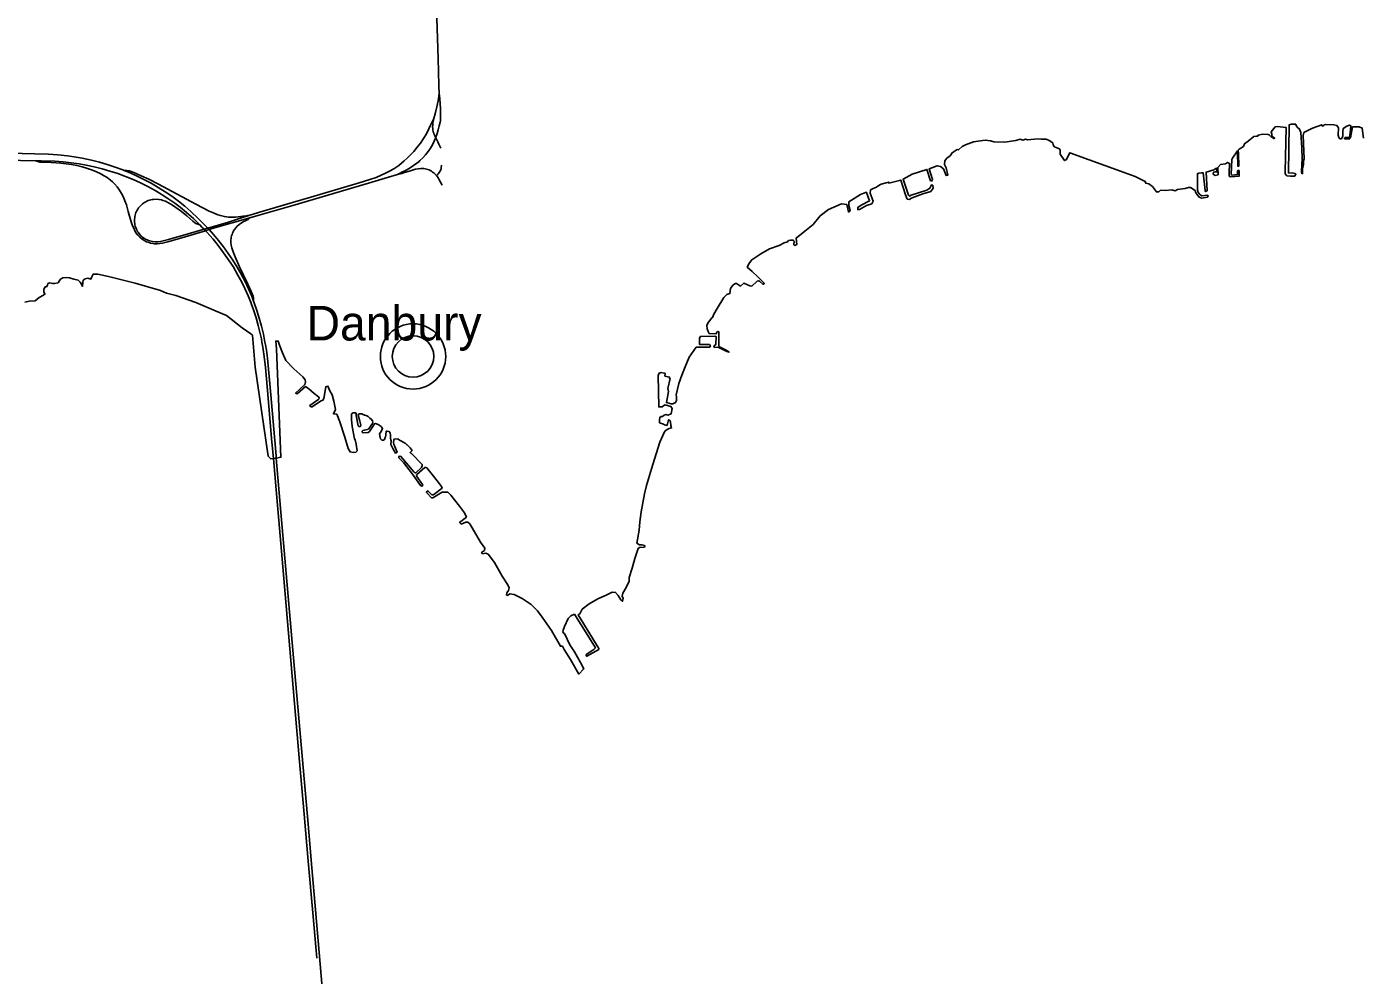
# Model space of a CAD drawing. Extents: x -82 to 873, y 0 to 440.
# Drawn here: x 481.74 to 521.91, y 142.41 to 170.93 of the extents above; entities that cross this region are included whole.
import ezdxf

# ---------------------------------------------------------------- set-up
doc = ezdxf.new("R2010")
doc.units = 0
for name, color, linetype in [('DV_X_Corp_Line', 7, 'Continuous'), ('GM_X_County', 7, 'Continuous'), ('GM_X_Interchange_Ramps', 7, 'Continuous'), ('GM_X_Interstate_Route', 7, 'Continuous')]:
    doc.layers.add(name, color=color, linetype=linetype)

msp = doc.modelspace()

# ---------------------------------------------------------------- linework, layer by layer
at = {"layer": 'DV_X_Corp_Line'}
for radius in [0.982, 0.623]:
    msp.add_circle((493.356, 161.017), radius, dxfattribs=at)
at = {"layer": 'GM_X_County'}
for points in [[(490.52, 159.73), (490.248, 159.54), (490.272, 159.511), (490.286, 159.499), (490.324, 159.504), (490.575, 159.674), (490.645, 159.703), (490.668, 159.755), (490.729, 160.106), (490.797, 160.124), (490.857, 159.984), (490.926, 159.864), (490.972, 159.674), (491.02, 159.424), (490.962, 159.295), (491.062, 159.284), (491.158, 159.047), (491.304, 158.589), (491.4, 158.251), (491.46, 158.145), (491.556, 158.13), (491.637, 158.135), (491.672, 158.178), (491.649, 158.381), (491.62, 158.512), (491.6, 158.536), (491.569, 158.697), (491.53, 158.908), (491.508, 159.119), (491.508, 159.289), (491.556, 159.319), (491.629, 159.326), (491.648, 159.311), (491.646, 159.242), (491.708, 158.932), (491.728, 158.912), (491.771, 158.912), (491.783, 158.946), (491.754, 159.067), (491.71, 159.251), (491.719, 159.278), (491.75, 159.293), (491.816, 159.287), (491.893, 159.256), (491.948, 159.24), (492.009, 159.207), (492.057, 159.165), (492.101, 159.132), (492.139, 159.078), (492.148, 159.042), (492.135, 159.005), (492.016, 158.835), (491.981, 158.82), (491.895, 158.802), (491.842, 158.789), (491.827, 158.772), (491.829, 158.745), (491.857, 158.725), (492.007, 158.732), (492.051, 158.761), (492.128, 158.882), (492.201, 158.992), (492.227, 159), (492.311, 158.967), (492.399, 158.906), (492.438, 158.851), (492.396, 158.761), (492.35, 158.69), (492.363, 158.578), (492.377, 158.541), (492.414, 158.501), (492.471, 158.503), (492.497, 158.517), (492.517, 158.583), (492.53, 158.593), (492.541, 158.657), (492.552, 158.767), (492.577, 158.77), (492.632, 158.756), (492.663, 158.739), (492.671, 158.715), (492.682, 158.657), (492.682, 158.56), (492.687, 158.512), (492.695, 158.479), (492.691, 158.369), (492.746, 158.254), (492.83, 158.111), (492.878, 158.138), (492.775, 158.375), (492.766, 158.419), (492.777, 158.516), (492.786, 158.532), (492.894, 158.538), (492.953, 158.501), (493.122, 158.406), (493.155, 158.369), (493.168, 158.369), (493.27, 158.268), (493.329, 158.188), (493.267, 158.133), (493.296, 158.098), (493.311, 158.098), (493.626, 157.764), (493.626, 157.729), (493.615, 157.678), (493.441, 157.522), (493.411, 157.519), (493.377, 157.548), (493.281, 157.672), (492.993, 158.01), (492.957, 158.021), (492.927, 158.008), (492.931, 157.964), (493.073, 157.829), (493.342, 157.475), (493.579, 157.132), (493.627, 157.113), (493.647, 157.146), (493.645, 157.17), (493.47, 157.411), (493.464, 157.441), (493.475, 157.466), (493.708, 157.676), (493.743, 157.679), (493.767, 157.669), (493.973, 157.417), (494.153, 157.189), (494.207, 157.107), (494.227, 157.055), (493.983, 156.865), (493.959, 156.854), (493.923, 156.858), (493.817, 156.952), (493.786, 156.971), (493.768, 156.96), (493.759, 156.924), (493.778, 156.903), (493.909, 156.768), (493.949, 156.765), (494.228, 156.939), (494.399, 156.939), (494.493, 156.85), (494.75, 156.513), (494.9, 156.318), (494.962, 156.186), (494.755, 156.028), (494.799, 155.974), (494.942, 156.038), (495.007, 156.033), (495.064, 155.981), (495.386, 155.436), (495.512, 155.256), (495.508, 155.184), (495.416, 155.125), (495.446, 155.082), (495.546, 155.099), (495.612, 155.072), (495.801, 154.825), (496.041, 154.407), (496.208, 154.15), (496.251, 154.063), (496.223, 153.978), (496.177, 153.908), (496.164, 153.847), (496.2, 153.832), (496.268, 153.883), (496.398, 153.861), (496.635, 153.738), (496.905, 153.56), (497.103, 153.365), (497.238, 153.176), (497.525, 152.779), (497.789, 152.3), (497.848, 152.304), (497.901, 152.201), (498.089, 151.902), (498.344, 151.463), (498.497, 151.624), (498.394, 151.812), (498.21, 152.13), (498.068, 152.342), (497.913, 152.683), (497.863, 152.72), (497.872, 152.786), (497.915, 152.895), (498.017, 153.136), (498.102, 153.218), (498.209, 153.262), (498.843, 152.254), (498.796, 152.2), (498.559, 152.052), (498.559, 152.014), (498.585, 152.001), (498.941, 152.206), (498.947, 152.231), (498.326, 153.247), (498.37, 153.278), (498.439, 153.414), (498.654, 153.582), (498.91, 153.723), (499.165, 153.839), (499.347, 153.929), (499.447, 153.92), (499.529, 153.831), (499.605, 153.701), (499.658, 153.657), (499.676, 153.74), (499.649, 153.81), (499.664, 153.898), (499.77, 154.073), (499.856, 154.256), (499.857, 154.365), (499.947, 154.651), (500.027, 154.937), (500.129, 155.243), (500.172, 155.276), (500.314, 155.28), (500.328, 155.298), (500.314, 155.336), (500.238, 155.354), (500.172, 155.349), (500.091, 155.406), (500.157, 155.79), (500.182, 156.046), (500.217, 156.348), (500.272, 156.614), (500.322, 156.885), (500.382, 157.135), (500.531, 157.637), (500.618, 157.924), (500.783, 158.44), (500.864, 158.636), (500.927, 158.766), (501.004, 158.816), (501.064, 158.849), (501.13, 158.869), (501.114, 158.939), (501.104, 159.052), (501.084, 159.095), (501.04, 159.115), (501.027, 159.075), (501.01, 158.989), (500.99, 158.942), (500.924, 158.965), (500.891, 158.985), (500.771, 159.022), (500.764, 159.112), (500.777, 159.185), (500.814, 159.215), (500.857, 159.215), (500.904, 159.251), (500.957, 159.268), (501.02, 159.248), (501.124, 159.295), (501.151, 159.457), (501.114, 159.511), (500.944, 159.558), (500.901, 159.538), (500.844, 159.498), (500.744, 159.498), (500.724, 160.446), (500.754, 160.519), (500.817, 160.539), (500.907, 160.516), (500.937, 160.506), (500.93, 160.426), (501.073, 160.396), (501.073, 160.353), (501.093, 160.35), (501.02, 160.057), (501.037, 159.967), (500.977, 159.628), (501.12, 159.588), (501.173, 159.588), (501.253, 159.631), (501.283, 159.694), (501.283, 159.807), (501.267, 159.867), (501.349, 160.202), (501.439, 160.458), (501.539, 160.709), (501.664, 161), (501.874, 161.295), (502.093, 161.301), (502.282, 161.292), (502.302, 161.335), (502.272, 161.375), (501.967, 161.377), (501.976, 161.57), (502, 161.621), (502.436, 161.628), (502.469, 161.621), (502.462, 161.373), (502.422, 161.351), (502.401, 161.321), (502.423, 161.287), (502.521, 161.293), (502.59, 161.267), (502.797, 161.163), (502.859, 161.142), (502.793, 161.194), (502.598, 161.295), (502.555, 161.339), (502.557, 161.754), (502.521, 161.771), (502.498, 161.748), (502.473, 161.702), (502.26, 161.705), (502.229, 161.769), (502.199, 161.848), (502.193, 161.946), (502.218, 162.021), (502.328, 162.171), (502.36, 162.188), (502.399, 162.288), (502.506, 162.464), (502.699, 162.794), (502.798, 162.882), (502.886, 162.906), (502.907, 163.066), (502.974, 163.161), (503.052, 163.214), (503.089, 163.208), (503.209, 163.133), (503.305, 163.224), (503.49, 163.146), (503.544, 163.133), (503.708, 163.279), (503.75, 163.292), (503.779, 163.278), (503.875, 163.196), (503.903, 163.194), (503.925, 163.21), (503.73, 163.414), (503.553, 163.571), (503.41, 163.699), (503.472, 163.835), (503.542, 163.927), (503.813, 164.106), (504.081, 164.252), (504.364, 164.355), (504.52, 164.434), (504.619, 164.465), (504.651, 164.501), (504.716, 164.517), (504.789, 164.518), (504.814, 164.485), (504.804, 164.376), (504.842, 164.357), (504.897, 164.383), (504.878, 164.577), (505.139, 164.788), (505.389, 164.984), (505.605, 165.245), (505.855, 165.435), (506.238, 165.605), (506.407, 165.587), (506.449, 165.365), (506.478, 165.368), (506.503, 165.41), (506.461, 165.557), (506.467, 165.672), (506.817, 165.89), (506.969, 165.947), (506.995, 165.95), (507.089, 165.694), (506.836, 165.567), (506.732, 165.501), (506.729, 165.435), (506.786, 165.438), (506.998, 165.555), (507.15, 165.609), (507.191, 165.685), (507.105, 165.925), (507.112, 166.026), (507.191, 166.067), (507.292, 166.105), (507.343, 166.153), (507.431, 166.2), (507.586, 166.241), (507.662, 166.264), (507.665, 166.232), (508.026, 166.324), (508.168, 165.878), (508.222, 165.751), (508.282, 165.735), (508.365, 165.786), (508.687, 165.906), (508.928, 165.976), (508.997, 166.083), (508.988, 166.166), (508.947, 166.175), (508.902, 166.074), (508.814, 166.014), (508.342, 165.865), (508.292, 165.836), (508.257, 165.868), (508.099, 166.352), (508.371, 166.498), (508.814, 166.643), (508.921, 166.302), (508.962, 166.295), (508.981, 166.336), (508.883, 166.665), (509.121, 166.754), (509.216, 166.735), (509.314, 166.656), (509.386, 166.457), (509.437, 166.469), (509.386, 166.688), (509.345, 166.792), (509.352, 166.896), (509.415, 166.982), (509.513, 167.055), (509.567, 167.143), (509.722, 167.238), (509.764, 167.231), (509.87, 167.327), (509.972, 167.381), (510.215, 167.472), (510.56, 167.52), (510.721, 167.498), (510.829, 167.469), (511.155, 167.463), (511.484, 167.51), (511.617, 167.552), (511.696, 167.523), (511.778, 167.555), (511.838, 167.529), (511.936, 167.542), (512.05, 167.555), (512.164, 167.561), (512.25, 167.552), (512.281, 167.555), (512.395, 167.552), (512.484, 167.517), (512.598, 167.441), (512.61, 167.384), (512.639, 167.327), (512.667, 167.311), (512.797, 167.261), (512.816, 167.223), (512.819, 167.099), (512.949, 166.909), (512.996, 166.932), (513.107, 167.144), (514.74, 166.552), (515.075, 166.426), (515.376, 166.277), (515.395, 166.229), (515.483, 166.21), (515.6, 166.125), (515.654, 166.049), (515.714, 165.967), (515.784, 165.973), (515.838, 166.017), (515.986, 166.005), (516.182, 166.03), (516.274, 166.002), (516.347, 166.037), (516.581, 166.071), (516.676, 166.097), (516.736, 166.1), (516.882, 166.008), (516.898, 165.942), (516.986, 165.821), (517.075, 165.78), (517.252, 165.812), (517.271, 165.85), (517.249, 165.872), (517.081, 165.853), (517.024, 165.888), (516.964, 165.97), (516.954, 166.062), (516.945, 166.511), (516.986, 166.53), (517.075, 166.543), (517.116, 166.54), (517.176, 166.011), (517.192, 165.976), (517.239, 166.002), (517.208, 166.555), (517.439, 166.628), (517.525, 166.679), (517.537, 166.571), (517.486, 166.571), (517.429, 166.555), (517.423, 166.499), (517.48, 166.457), (517.571, 166.483), (517.564, 166.702), (517.638, 166.786), (517.793, 166.815), (517.856, 166.853), (517.916, 166.824), (517.904, 166.53), (517.904, 166.442), (517.945, 166.419), (518.198, 166.438), (518.198, 166.594), (518.179, 166.622), (518.15, 166.597), (518.154, 166.486), (517.992, 166.473), (517.964, 166.492), (517.983, 166.945), (518.002, 166.986), (518.153, 167.201), (518.153, 167.144), (518.163, 166.739), (518.188, 166.736), (518.179, 167.112), (518.174, 167.222), (518.202, 167.248), (518.33, 167.336), (518.359, 167.416), (518.476, 167.495), (518.644, 167.634), (518.723, 167.641), (518.761, 167.641), (518.777, 167.676), (518.919, 167.707), (519.071, 167.688), (519.109, 167.682), (519.156, 167.631), (519.245, 167.568), (519.273, 167.587), (519.185, 167.666), (519.185, 167.698), (519.163, 167.774), (519.283, 167.922), (519.356, 167.929), (519.438, 167.922), (519.621, 167.9), (519.59, 166.568), (519.587, 166.508), (519.637, 166.448), (519.745, 166.435), (519.872, 166.439), (519.906, 166.486), (519.887, 166.524), (519.792, 166.54), (519.688, 166.53), (519.704, 167.983), (519.77, 168.005), (519.903, 168.002), (519.903, 167.979), (519.951, 167.913), (520.02, 167.856), (520.058, 167.752), (520.083, 167.293), (520.102, 166.958), (520.087, 166.79), (520.074, 166.575), (520.087, 166.511), (520.112, 166.515), (520.106, 166.581), (520.106, 166.663), (520.14, 166.787), (520.137, 166.897), (520.159, 166.964), (520.128, 167.66), (520.144, 167.749), (520.406, 167.888), (520.685, 167.986), (520.7, 167.957), (520.729, 167.945), (520.76, 167.98), (520.798, 167.995), (521.055, 167.986), (521.143, 167.967), (521.191, 167.891), (521.185, 167.668), (521.197, 167.606), (521.232, 167.565), (521.279, 167.565), (521.32, 167.638), (521.324, 167.787), (521.333, 167.875), (521.441, 167.945), (521.523, 167.973), (521.57, 167.945), (521.555, 167.872), (521.555, 167.825), (521.517, 167.603), (521.39, 167.603), (521.371, 167.587), (521.374, 167.565), (521.507, 167.552), (521.555, 167.594), (521.615, 167.923), (521.722, 167.926), (521.817, 167.92), (521.903, 167.885), (521.947, 167.586)], [(481.683, 162.65), (481.807, 162.676), (481.99, 162.695), (482.11, 162.786), (482.218, 162.852), (482.285, 162.888), (482.253, 162.963), (482.248, 163.039), (482.293, 163.11), (482.33, 163.115), (482.362, 163.159), (482.372, 163.207), (482.43, 163.233), (482.516, 163.216), (482.575, 163.216), (482.678, 163.233), (482.717, 163.279), (482.754, 163.34), (482.827, 163.377), (482.935, 163.388), (483.026, 163.385), (483.152, 163.346), (483.283, 163.311), (483.345, 163.254), (483.383, 163.191), (483.414, 163.122), (483.422, 163.245), (483.434, 163.311), (483.49, 163.351), (483.579, 163.376), (483.67, 163.346), (483.689, 163.39), (483.731, 163.488), (483.873, 163.493), (484.192, 163.423), (485.003, 163.217), (485.758, 163), (485.94, 162.925), (486.222, 162.849), (486.821, 162.638), (487.436, 162.381), (487.743, 162.25), (488.218, 161.876), (488.481, 161.695), (488.532, 161.657), (488.61, 160.693), (489, 158.018), (489.077, 157.936), (489.156, 157.948), (489.242, 157.961), (489.383, 157.986), (489.251, 161.242), (489.225, 161.482), (489.301, 161.482), (489.339, 161.361), (489.427, 161.124), (489.528, 160.893), (489.773, 160.65), (490.039, 160.407), (490.107, 160.311), (490.117, 160.25), (490.097, 160.177), (489.95, 160.038), (489.821, 159.917), (489.867, 159.894), (490.125, 160.111), (490.223, 160.043), (490.38, 159.904), (490.511, 159.798), (490.528, 159.773), (490.52, 159.73)]]:
    msp.add_lwpolyline(points, dxfattribs=at)
at = {"layer": 'GM_X_Interchange_Ramps'}
for points in [[(493.981, 168.171), (493.966, 168.101), (493.954, 168.028), (493.948, 167.969), (493.945, 167.921), (493.948, 167.871), (493.954, 167.833), (493.966, 167.775), (493.979, 167.731), (493.994, 167.693), (494.012, 167.653), (494.038, 167.6), (494.044, 167.589), (494.062, 167.556), (494.1, 167.476), (494.133, 167.407), (494.189, 167.277)], [(482.008, 166.905), (482.075, 166.879), (482.131, 166.865), (482.168, 166.862), (482.31, 166.86), (482.474, 166.851), (482.76, 166.833), (482.923, 166.814), (483.085, 166.788), (483.245, 166.756), (483.405, 166.718), (483.562, 166.672), (483.717, 166.618), (483.831, 166.573), (483.943, 166.522), (484.051, 166.464), (484.155, 166.398), (484.253, 166.324), (484.314, 166.27), (484.373, 166.212), (484.453, 166.12), (484.526, 166.021), (484.589, 165.916), (484.645, 165.806), (484.692, 165.693), (484.733, 165.577), (484.793, 165.381), (484.883, 165.065), (484.923, 164.949), (484.954, 164.873), (484.99, 164.8), (485.033, 164.73), (485.081, 164.664), (485.137, 164.604), (485.2, 164.551), (485.268, 164.506), (485.34, 164.468), (485.417, 164.44), (485.457, 164.429), (485.537, 164.414), (485.578, 164.409), (485.659, 164.408), (485.741, 164.414), (485.822, 164.427), (485.981, 164.464), (486.336, 164.567), (487.113, 164.8), (487.225, 164.834), (487.316, 164.861), (488.446, 165.183)], [(494.214, 166.766), (494.202, 166.69), (494.197, 166.665), (494.19, 166.642), (494.178, 166.612), (494.163, 166.577), (494.143, 166.545), (494.122, 166.516), (494.106, 166.497), (494.09, 166.481), (494.063, 166.455)], [(488.422, 165.253), (488.378, 165.254), (488.339, 165.251), (488.24, 165.234), (488.175, 165.224), (488.1, 165.217), (488.017, 165.211), (487.901, 165.206), (487.807, 165.207), (487.685, 165.226), (487.565, 165.254), (487.486, 165.279), (487.372, 165.323), (487.223, 165.392), (486.822, 165.601), (485.698, 166.199), (485.406, 166.349), (485.183, 166.454), (484.957, 166.552), (484.878, 166.585), (484.833, 166.598), (484.746, 166.609), (484.665, 166.612)], [(492.892, 166.49), (493.015, 166.517), (493.073, 166.535), (493.309, 166.612), (493.429, 166.646), (493.511, 166.663), (493.593, 166.672), (493.635, 166.672), (493.676, 166.67), (493.717, 166.664), (493.758, 166.655), (493.798, 166.643), (493.836, 166.628), (493.874, 166.609), (493.909, 166.589), (493.944, 166.565), (493.977, 166.54), (494.005, 166.515), (494.037, 166.483), (494.063, 166.455), (494.091, 166.419), (494.115, 166.385), (494.136, 166.35), (494.186, 166.263), (494.232, 166.174)], [(488.422, 165.253), (488.195, 165.183), (487.99, 165.121), (487.803, 165.06), (487.185, 164.877), (487.071, 164.844), (486.593, 164.702), (486.004, 164.53), (485.885, 164.5), (485.764, 164.477), (485.683, 164.469), (485.601, 164.468), (485.52, 164.476), (485.48, 164.483), (485.44, 164.493), (485.401, 164.506), (485.363, 164.521), (485.326, 164.538), (485.256, 164.58), (485.223, 164.605), (485.192, 164.631), (485.162, 164.659), (485.134, 164.689), (485.109, 164.721), (485.085, 164.754), (485.063, 164.789), (485.044, 164.825), (485.027, 164.863), (485.001, 164.94), (484.992, 164.98), (484.985, 165.02), (484.981, 165.061), (484.979, 165.102), (484.98, 165.143), (484.984, 165.184), (484.99, 165.224), (484.998, 165.264), (485.01, 165.304), (485.023, 165.342), (485.04, 165.38), (485.058, 165.416), (485.079, 165.451), (485.103, 165.485), (485.128, 165.517), (485.155, 165.547), (485.184, 165.576), (485.215, 165.603), (485.282, 165.65), (485.318, 165.67), (485.354, 165.688), (485.392, 165.704), (485.431, 165.717), (485.47, 165.728), (485.511, 165.736), (485.551, 165.742), (485.633, 165.746), (485.714, 165.74), (485.794, 165.724), (485.834, 165.712), (485.91, 165.683), (485.983, 165.647), (486.089, 165.584), (486.225, 165.494), (486.39, 165.373), (486.55, 165.245), (486.737, 165.086), (486.785, 165.042), (486.82, 165.02), (486.943, 164.975)]]:
    msp.add_lwpolyline(points, dxfattribs=at)
at = {"layer": 'GM_X_Interstate_Route'}
for points in [[(494.117, 169.605), (494.098, 170.291), (494.093, 170.577), (494.068, 171.191), (494.038, 172.379), (494.011, 173.828)], [(494.184, 168.108), (494.182, 168.257), (494.178, 168.48), (494.172, 168.596), (494.167, 168.67), (494.163, 168.714), (494.157, 168.763), (494.14, 168.932), (494.129, 169.144), (494.117, 169.605)], [(488.422, 165.253), (488.712, 165.343), (488.878, 165.394), (489.732, 165.644), (490.283, 165.807), (491.739, 166.237), (492.052, 166.336), (492.246, 166.404), (492.399, 166.466), (492.511, 166.518), (492.648, 166.588), (492.776, 166.662), (492.931, 166.763), (493.085, 166.897), (493.175, 166.977), (493.264, 167.062), (493.377, 167.181), (493.483, 167.307), (493.582, 167.437), (493.674, 167.574), (493.758, 167.715), (493.834, 167.861), (493.885, 167.973), (493.981, 168.171), (494.031, 168.358), (494.072, 168.521), (494.093, 168.62), (494.109, 168.71), (494.118, 168.776), (494.127, 168.842), (494.14, 168.932)], [(492.614, 166.406), (492.892, 166.49), (492.97, 166.534), (493.016, 166.557), (493.09, 166.591), (493.17, 166.628), (493.271, 166.691), (493.374, 166.757), (493.472, 166.829), (493.536, 166.883), (493.564, 166.908), (493.652, 166.993), (493.734, 167.083), (493.81, 167.179), (493.878, 167.279), (493.939, 167.385), (493.993, 167.494), (494.038, 167.6), (494.043, 167.612), (494.081, 167.721), (494.114, 167.838), (494.145, 167.952), (494.173, 168.064), (494.184, 168.108)], [(480.828, 167.141), (481.978, 167.115), (482.388, 167.098), (482.674, 167.078), (482.96, 167.05), (483.163, 167.023), (483.405, 166.98), (483.686, 166.919), (483.925, 166.859), (484.161, 166.791), (484.394, 166.714), (484.625, 166.628), (484.665, 166.612), (484.853, 166.535), (485.077, 166.434), (485.261, 166.343), (485.478, 166.227), (485.69, 166.103), (485.899, 165.973), (486.102, 165.834), (486.301, 165.689), (486.494, 165.536), (486.673, 165.38), (486.898, 165.166), (487.055, 165.008), (487.185, 164.877), (487.207, 164.854), (487.225, 164.834), (487.356, 164.685), (487.507, 164.505), (487.656, 164.316), (487.799, 164.116), (487.936, 163.912), (488.065, 163.703), (488.187, 163.49), (488.302, 163.273), (488.408, 163.052), (488.505, 162.826), (488.56, 162.685), (488.579, 162.635), (488.659, 162.403), (488.732, 162.168), (488.797, 161.931), (488.854, 161.692), (488.903, 161.451), (488.916, 161.371), (488.944, 161.209), (488.977, 160.966), (489.011, 160.64), (489.08, 159.864), (489.237, 158.025), (489.242, 157.961), (489.404, 156.104), (489.744, 152.18), (490.199, 146.95), (490.311, 145.642), (490.421, 144.375), (490.907, 138.767)], [(480.61, 166.935), (482.008, 166.905), (482.172, 166.901), (482.583, 166.886), (482.829, 166.869), (483.075, 166.843), (483.319, 166.808), (483.522, 166.772), (483.764, 166.721), (484.004, 166.663), (484.241, 166.595), (484.476, 166.518), (484.708, 166.432), (484.936, 166.338), (485.161, 166.235), (485.382, 166.124), (485.599, 166.006), (485.779, 165.899)], [(488.446, 165.183), (488.763, 165.274), (488.972, 165.334), (489.739, 165.556), (492.018, 166.226), (492.614, 166.406)], [(485.779, 165.899), (485.811, 165.88), (485.984, 165.769), (486.187, 165.627), (486.352, 165.504), (486.544, 165.348), (486.748, 165.166), (486.904, 165.016), (486.943, 164.975)], [(488.56, 162.685), (488.559, 162.751), (488.556, 162.794), (488.546, 162.829), (488.487, 162.969), (488.385, 163.194), (488.138, 163.713), (488.002, 164.012), (487.942, 164.165), (487.906, 164.283), (487.889, 164.364), (487.88, 164.445), (487.879, 164.527), (487.883, 164.568), (487.89, 164.609), (487.899, 164.649), (487.911, 164.688), (487.925, 164.727), (487.942, 164.764), (487.961, 164.8), (487.983, 164.835), (488.033, 164.899), (488.061, 164.929), (488.123, 164.984), (488.19, 165.031), (488.261, 165.073), (488.313, 165.098), (488.369, 165.126), (488.393, 165.14), (488.421, 165.16), (488.446, 165.183)], [(486.943, 164.975), (487.007, 164.909)], [(487.007, 164.909), (487.071, 164.844), (487.113, 164.8), (487.158, 164.754), (487.347, 164.541), (487.467, 164.397), (487.608, 164.208), (487.76, 163.989), (487.948, 163.718), (488.089, 163.467), (488.205, 163.249), (488.295, 163.064), (488.396, 162.839), (488.485, 162.619)], [(488.485, 162.619), (488.488, 162.61), (488.559, 162.417), (488.634, 162.182), (488.702, 161.944), (488.751, 161.744), (488.794, 161.543), (488.81, 161.449), (488.836, 161.3), (488.877, 161.015), (488.915, 160.688), (488.967, 160.116), (489.113, 158.439), (489.156, 157.948), (489.239, 157.007), (489.397, 155.166), (489.794, 150.583), (489.936, 148.947), (490.083, 147.255)], [(490.083, 147.255), (490.206, 145.838), (490.342, 144.284), (490.461, 142.917)]]:
    msp.add_lwpolyline(points, dxfattribs=at)

# ---------------------------------------------------------------- texts
at = {"layer": 'DV_X_Corp_Line'}
msp.add_text('Danbury', height=1.0417, rotation=0.005, dxfattribs=at).set_placement((490.154, 161.498))

doc.saveas('drawing.dxf')
